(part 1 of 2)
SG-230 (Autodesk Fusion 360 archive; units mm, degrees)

design "OP-1042" references "OP-1042-D", "OP-1040_C", "Washer DIN 125-2 - A 2.2 Steel 100 HV Plain", "OP-1042-J", "OP-1042-M_1", "OP-1042-H", "OP-1042-L_1", "Śruba metryczna M3x10", "Sprezyna naciskowa", "OP-1042-R", "Stożkowy do blach 2,2x6,5", "Do tworzyw 2,2x8", "OP-1040_A_1", "OP-1042-A", "SZKLO OP-1040", "OP-1042-C_1", "Śruba metryczna; M3x5mm-H", "OP-1042-C", "Śruba metryczna; M2x8mm-H", "Uziemienie gnioazdko", "OP-1042-B", "Spring Lock Washer DIN 127 - B 2 Steel 100 HV Plain", "Sprężyna skrętna 1042", "OP-1042-O", "OP-1042-G", "Spring Lock Washer DIN 127 - B 3 Steel 100 HV Plain", "OP-1042-S", "OP-1042-M", "Washer DIN 433-1 - 3.2 - A Steel 100 HV Plain", "bolec", "Hexagon Thin Nut DIN 439-2 - M2 x 0.4 Steel 6 Plain", "B3/BN1046", "OP-1042-L", "OP-1042-F", "OP-1042-P", "OP-1042-H_1", "OP-1040_przycisk", "OP-1042-N", "OP-1040_A", "OP-1040_F"
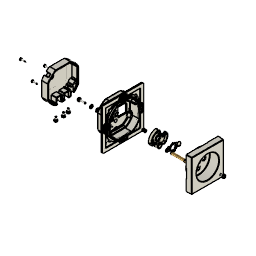
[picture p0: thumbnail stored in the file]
description: https://chmura.techlocal.pl/index.php/s/TPQ2T6wTG2s9XiP
part number: OP-1042 WER.10
component_insert "Component Insert1"
component_insert "Component Insert4"
component_insert "Component Insert5"
component_insert "Component Insert6"
component_insert "Component Insert7"
component_insert "Component Insert8"
component_insert "Component Insert9"
component_insert "Component Insert10"
component_insert "Component Insert11"
component_insert "Component Insert12"
component_insert "Component Insert13"
component_insert "Component Insert14"
component_insert "Component Insert15"
component_insert "Component Insert16"
component_insert "Component Insert17"
component_insert "Component Insert18"
component_insert "Component Insert19"
component_insert "Component Insert20"
joint "Assemble1" alignAngle 0 alignOffsetX 0 alignOffsetY 0 alignOffsetZ 0
component_insert "Component Insert21"
joint "Assemble2" alignAngle 0 alignOffsetX 0 alignOffsetY 0 alignOffsetZ 0
step "Washer1"
joint "Assemble3" alignAngle 0 alignOffsetX 0 alignOffsetY 0 alignOffsetZ 0
step "Washer2"
joint "Assemble4" alignAngle 90 alignOffsetX 0 alignOffsetY 0 alignOffsetZ 0
step "Nut"
joint "Assemble5" alignAngle 0 alignOffsetX 0 alignOffsetY 0 alignOffsetZ 0
step "Screw4"
joint "Assemble6" alignAngle 0 alignOffsetX 0 alignOffsetY 0 alignOffsetZ -1.3
component_insert "Component Insert22"
joint "Assemble7" alignAngle 90 alignOffsetX 0 alignOffsetY 0 alignOffsetZ 0 RotateMinimum 270 RotateMaximum 270
step "Screw5"
joint "Assemble9" alignAngle 0 alignOffsetX 0 alignOffsetY 0 alignOffsetZ 0
step "Screw6"
joint "Assemble10" alignAngle 0 alignOffsetX 0 alignOffsetY 0 alignOffsetZ 0
step "Screw7"
joint "Assemble11" alignAngle 0 alignOffsetX 0 alignOffsetY 0 alignOffsetZ 0
step "Screw8"
joint "Assemble12" alignAngle 0 alignOffsetX 0 alignOffsetY 0 alignOffsetZ 0
step "Screw9"
joint "Assemble13" alignAngle 0 alignOffsetX 0 alignOffsetY 0 alignOffsetZ 0
step "Screw11"
joint "Assemble16" alignAngle 180 alignOffsetX 0 alignOffsetY 0 alignOffsetZ -1
step "Screw12"
joint "Assemble17" alignAngle 180 alignOffsetX 0 alignOffsetY 0 alignOffsetZ -1
joint "Assemble18" alignAngle 0 alignOffsetX 0 alignOffsetY 0 alignOffsetZ 0
joint "Assemble19" alignAngle 0 alignOffsetX 0 alignOffsetY 0 alignOffsetZ 0
joint "Assemble20" alignAngle 0 alignOffsetX 0 alignOffsetY 0 alignOffsetZ 0
joint "Assemble21" alignAngle 0 alignOffsetX 0 alignOffsetY 0 alignOffsetZ 0
joint "Assemble22" alignAngle 180 alignOffsetX 0 alignOffsetY 0 alignOffsetZ -1
joint "Assemble23" alignAngle 180 alignOffsetX 0 alignOffsetY 0 alignOffsetZ -1
joint "Assemble24" alignAngle -90 alignOffsetX 0 alignOffsetY 0 alignOffsetZ 0
joint "Assemble25" alignAngle -90 alignOffsetX 0 alignOffsetY 0 alignOffsetZ 0
joint "Assemble26" alignAngle 0 alignOffsetX 0 alignOffsetY 0 alignOffsetZ 0
joint "Assemble27" alignAngle 180 alignOffsetX 0 alignOffsetY 0 alignOffsetZ -1
joint "Assemble28" alignAngle 180 alignOffsetX 0 alignOffsetY 0 alignOffsetZ -1
joint "Assemble29" alignAngle 250 alignOffsetX -2.5 alignOffsetY 0.5 alignOffsetZ 0
joint "Assemble30" alignAngle 0 alignOffsetX 0 alignOffsetY 0 alignOffsetZ 0
joint "Assemble31" alignAngle 0 alignOffsetX 0 alignOffsetY 0 alignOffsetZ 0
joint "Assemble32" alignAngle 180 alignOffsetX 0 alignOffsetY 0 alignOffsetZ -1
joint "Assemble33" alignAngle 180 alignOffsetX 0 alignOffsetY 0 alignOffsetZ -1
joint "Assemble34" alignAngle 0 alignOffsetX 0 alignOffsetY 0 alignOffsetZ 6
step "Screw14"
joint "Assemble35" alignAngle 180 alignOffsetX 0 alignOffsetY 0 alignOffsetZ -2.5
step "Screw16"
joint "Assemble36" alignAngle 180 alignOffsetX 0 alignOffsetY 0 alignOffsetZ -2.5
step "Screw17"
joint "Assemble37" alignAngle 180 alignOffsetX 0 alignOffsetY 0 alignOffsetZ -2.5
component_insert "Component Insert24"
joint "Assemble38" alignAngle 0 alignOffsetX 0 alignOffsetY 0 alignOffsetZ -1.6
joint "Assemble39" alignAngle 0 alignOffsetX 0 alignOffsetY 0 alignOffsetZ 0
joint "Assemble40" alignAngle 0 alignOffsetX 0 alignOffsetY 0 alignOffsetZ 0
joint "Assemble41" alignAngle 0 alignOffsetX 0 alignOffsetY 0 alignOffsetZ 0
component_insert "Component Insert25"
joint "Assemble42" alignAngle 180 alignOffsetX 0 alignOffsetY 0 alignOffsetZ -12.6
step "Screw18"
joint "Assemble43" alignAngle 0 alignOffsetX 0 alignOffsetY 0 alignOffsetZ -2.6
component_insert "Component Insert26"
component_insert "Component Insert27"
component_insert "Component Insert28"
component_insert "Component Insert29"
joint "Assemble44" alignAngle 0 alignOffsetX 0 alignOffsetY 0 alignOffsetZ 0
joint "Assemble45" alignAngle 0 alignOffsetX 0 alignOffsetY 0 alignOffsetZ 0
component_insert "Component Insert30"
joint "Assemble46" alignAngle 0 alignOffsetX 0 alignOffsetY 0 alignOffsetZ -1.5
joint "Assemble47" alignAngle 180 alignOffsetX 0 alignOffsetY 0 alignOffsetZ -2.5
joint "Assemble48" alignAngle 180 alignOffsetX 0 alignOffsetY 0 alignOffsetZ 2.5
joint "Assemble49" alignAngle 180 alignOffsetX 0 alignOffsetY 0 alignOffsetZ 2.5
joint "Assemble50" alignAngle 0 alignOffsetX 0 alignOffsetY 0 alignOffsetZ 0
component_insert "Component Insert31"
component_insert "Component Insert32"
component_insert "Component Insert33"
joint "Assemble51" alignAngle 0 alignOffsetX 0 alignOffsetY 0 alignOffsetZ 0
joint "Assemble52" alignAngle 0 alignOffsetX 0 alignOffsetY 0 alignOffsetZ 0
component_insert "Component Insert34"
component_insert "Component Insert35"
joint "Assemble53" alignAngle -180 alignOffsetX 0 alignOffsetY 0 alignOffsetZ 0
joint "Assemble54" alignAngle 0 alignOffsetX 0 alignOffsetY 0 alignOffsetZ 0
joint "Assemble55" alignAngle 0 alignOffsetX 0 alignOffsetY 0 alignOffsetZ -1.6
component_insert "Component Insert36"
joint "Assemble57" alignAngle 180 alignOffsetX 0.05 alignOffsetY -0.05 alignOffsetZ -1.8
joint "Assemble58" alignAngle 0 alignOffsetX 0 alignOffsetY 0 alignOffsetZ -1.6
joint "Assemble59" alignAngle 0 alignOffsetX 0 alignOffsetY 0 alignOffsetZ 0
joint "Assemble60" alignAngle 0 alignOffsetX 0 alignOffsetY 0 alignOffsetZ 0
joint "Assemble61" alignAngle 0 alignOffsetX 0 alignOffsetY 0 alignOffsetZ 0
joint "Assemble62" alignAngle 0 alignOffsetX 0 alignOffsetY 0 alignOffsetZ -1.6
joint "Assemble63" alignAngle 0 alignOffsetX 0 alignOffsetY 0 alignOffsetZ 0
joint "Assemble64" alignAngle -90 alignOffsetX 0 alignOffsetY 0 alignOffsetZ 0
joint "Assemble65" alignAngle 180 alignOffsetX 0 alignOffsetY 0 alignOffsetZ 3.5
joint "Assemble66" alignAngle 180 alignOffsetX 0 alignOffsetY 0 alignOffsetZ 3.5
joint "Assemble67" alignAngle 180 alignOffsetX 0 alignOffsetY 0 alignOffsetZ 3.5
joint "Assemble68" alignAngle 180 alignOffsetX 0 alignOffsetY 0 alignOffsetZ 3.5
joint "Assemble69" alignAngle 0 alignOffsetX 0 alignOffsetY 0 alignOffsetZ 0
joint "Assemble70" alignAngle -90 alignOffsetX 0 alignOffsetY 0 alignOffsetZ 0
joint "Assemble71" alignAngle 0 alignOffsetX 0 alignOffsetY 0 alignOffsetZ 0
joint "Assemble72" alignAngle 0 alignOffsetX 0 alignOffsetY 0 alignOffsetZ -0.1
joint "Assemble73" alignAngle 0 alignOffsetX 0 alignOffsetY 0 alignOffsetZ -1.6
joint "Assemble74" alignAngle 0 alignOffsetX 0 alignOffsetY 0 alignOffsetZ 0
joint "Assemble75" alignAngle 0 alignOffsetX 0 alignOffsetY 0 alignOffsetZ 0
joint "Assemble76" alignAngle 0 alignOffsetX 0 alignOffsetY 0 alignOffsetZ -1.6
joint "Assemble77" alignAngle 0 alignOffsetX 0 alignOffsetY 0 alignOffsetZ 0
component_insert "Component Insert37"
joint "Assemble78" alignAngle 0 alignOffsetX 0 alignOffsetY -1.2 alignOffsetZ 0
step "Washer19"
joint "Assemble79" alignAngle 0 alignOffsetX 0 alignOffsetY 0 alignOffsetZ 0
step "Washer20"
joint "Assemble80" alignAngle 0 alignOffsetX 0 alignOffsetY 0 alignOffsetZ 0
joint "Assemble81" alignAngle 0 alignOffsetX 0 alignOffsetY 0 alignOffsetZ -1.6
joint "Assemble82" alignAngle 0 alignOffsetX 0 alignOffsetY 0 alignOffsetZ 0

design "OP-1042-R" references "OP-1042-B"
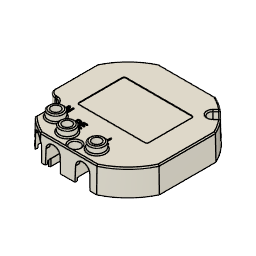
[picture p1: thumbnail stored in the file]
description: arrangementsContainer
external_derived "ExternalDerived1" AlongDistance -1.6 TaperAngle 0 Radius 0.5 Radius 0.5 Radius 2 Radius 1 Linear Dimension-2 20.6 AlongDistance 0.2 TaperAngle 0 Radius 0.8 Radius 0.5 distance 0.9 Radius 0.5 Radius 2 Radius 0.5
step "RemoveFeatures"
step "RemoveFaces1"
step "RemoveFaces2"
fillet "Fillet1" radius 1.25
fillet "Fillet2" radius 2
delete_face "DeleteFace1"
delete_face "DeleteFace2"
delete_face "DeleteFace3"
delete_face "DeleteFace4"
delete_face "DeleteFace5"
delete_face "DeleteFace6"
move_face "MoveFace1"
delete_face "DeleteFace7"
delete_face "DeleteFace8"
offset_faces "OffsetFaces1" distance -13.2
delete_face "DeleteFace9"
move_face "MoveFace2"
move_face "MoveFace3"
move_face "MoveFace4"
fillet "Fillet3" radius 0.5
fillet "Fillet4" radius 0.5
fillet "Fillet5" radius 0.5
fillet "Fillet6" radius 0.5
move_face "MoveFace5"
move_face "MoveFace6"
delete_face "DeleteFace10"
delete_face "DeleteFace11"
move_face "MoveFace7"
sketch "Sketch1" plane through (0, 11.5, 0) normal (0, 1, 0) x axis (-1, 0, 0)
  line L1 (19.3053, -24.5348) -> (19.3053, -43.5348)
  line L2 (50.1053, -22.7348) -> (21.1053, -22.7348)
  line L3 (51.9053, -43.5348) -> (51.9053, -24.5348)
  line L4 (21.1053, -45.3348) -> (50.1053, -45.3348)
  line L5 (41.5666, -61.7513) -> (30.2276, -61.7513)
  line L6 (54.8327, -23.9147) -> (54.8327, -48.4853)
  line L7 (49.8995, -19.4417) -> (51.1656, -18.1756)
  line L8 (47.3056, -14.3156) -> (46.0395, -15.5817)
  line L9 (16.9961, -10.6487) -> (41.5666, -10.6487)
  line L10 (3.73, -42.1572) -> (3.73, -23.9147)
  line L11 (7.1507, -44.9069) -> (6.4792, -44.9069)
  line L12 (9.8879, -56.8807) -> (9.8879, -47.7002)
  line L13 (27.733, -61.7513) -> (16.9961, -61.7513)
  curve K1
  curve K2
  curve K3
  curve K4
  curve K5
  curve K6
  curve K7
  curve K8
  curve K9
  curve K10
  curve K11
  curve K12
  circle C1 centre (22.4803, -56.1272) radius 3.8852
  arc A1 centre (21.1053, -43.5348) radius 1.8 clockwise from (21.1053, -45.3348) to (19.3053, -43.5348)
  arc A2 centre (21.1053, -24.5348) radius 1.8 clockwise from (19.3053, -24.5348) to (21.1053, -22.7348)
  arc A3 centre (50.1053, -24.5348) radius 1.8 clockwise from (50.1053, -22.7348) to (51.9053, -24.5348)
  arc A4 centre (50.1053, -43.5348) radius 1.8 clockwise from (51.9053, -43.5348) to (50.1053, -45.3348)
  arc A5 centre (29.2814, -36.2) radius 28.3513 clockwise from (54.8327, -48.4853) to (41.5666, -61.7513)
  arc A6 centre (29.2814, -36.2) radius 28.3513 clockwise from (51.1656, -18.1756) to (54.8327, -23.9147)
  arc A7 centre (47.9695, -17.5117) radius 2.7294 clockwise from (49.8995, -19.4417) to (46.0395, -15.5817)
  arc A8 centre (29.2814, -36.2) radius 28.3513 clockwise from (41.5666, -10.6487) to (47.3056, -14.3156)
  arc A9 centre (29.2814, -36.2) radius 28.3513 clockwise from (3.73, -23.9147) to (16.9961, -10.6487)
  closed curve K13 centre (6.4805, -42.1559)
  arc A10 centre (7.094, -47.7002) radius 2.7939 clockwise from (7.1507, -44.9069) to (9.8879, -47.7002)
  arc A11 centre (29.2814, -36.2) radius 28.3513 clockwise from (16.9961, -61.7513) to (9.8879, -56.8807)
  arc A12 centre (28.9803, -59.2217) radius 2.8204 clockwise from (27.733, -61.7513) to (30.2276, -61.7513)
  circle C2 centre (14.2237, -52.8962) radius 3.8852
  circle C3 centre (35.4803, -56.1272) radius 3.8852
  point P38 (14.2237, -52.8962)
  point P2 (22.4803, -56.1272)
  point P39 (35.4803, -56.1272)
  vertical P38
  vertical K2
  vertical K6
  vertical K10
  vertical P2
  vertical P39
  equal K1 K2
  equal K5 K6
  equal K9 K10
  equal K5 K9
  equal K1 K5
  dimension "d18" distance P2 K5 = 3 (= "d19")
  dimension "d19" distance P38 K1 = 3
  dimension "d20" distance P39 K9 = 3 (= "d19")
  dimension "d14" Text1-Height = 3
  dimension "d15" Text2-Height = 3
  dimension "d16" Text3-Height = 3
  dimension "d17" distance = 5
delete_face "DeleteFace12"
delete_face "DeleteFace13"
delete_face "DeleteFace14"
extrude "Extrude1" add sketch "Sketch1" along normal blind 0.2
offset_faces "OffsetFaces2" distance -0.2
delete_face "DeleteFace15"
move_face "MoveFace8"
move_face "MoveFace10"
delete_face "DeleteFace16"
fillet "Fillet7" radius 0.5
offset_faces "OffsetFaces3" distance -0.03
draft "Draft1" Angle1 1 Angle2 0
move_face "MoveFace11"
extrude "Extrude2" new body of existing geometry blind 0.2
delete_face "DeleteFace17"
combine "Combine2"
sketch "Sketch7" plane through (0, 9.9, 0) normal (0, -1, 0) x axis (1, 0, 0)
  curve K1 (-9.9653, -17.8349) -> (-9.2431, -17.8508)
  line L1 (-10.4951, -18.3647) -> (-9.9653, -17.8349)
  line L2 (-11.4461, -18.1208) -> (-11.2022, -18.3647)
  line L3 (-10.9163, -16.884) -> (-11.4461, -17.4137)
  curve K2 (-10.9321, -16.1617) -> (-10.9163, -16.884)
  line L4 (-41.2944, -11.8297) -> (-17.2683, -11.8297)
  line L5 (-53.6517, -48.2131) -> (-53.6517, -24.1869)
  curve K3 (-48.5974, -54.5651) -> (-49.3197, -54.5492)
  line L6 (-48.0676, -54.0353) -> (-48.5974, -54.5651)
  line L7 (-47.1167, -54.2792) -> (-47.3605, -54.0353)
  line L8 (-47.6464, -55.516) -> (-47.1167, -54.9863)
  curve K4 (-47.6306, -56.2383) -> (-47.6464, -55.516)
  line L9 (-40.6976, -60.5703) -> (-41.2944, -60.5703)
  line L10 (-40.1976, -52.3597) -> (-40.1976, -60.0705)
  line L11 (-31.2628, -51.8599) -> (-39.6978, -51.8599)
  line L12 (-30.763, -55.6438) -> (-30.763, -52.3597)
  curve K5 (-30.0943, -56.1143) -> (-30.763, -55.6438)
  curve K6 (-27.1976, -55.6438) -> (-27.8663, -56.1143)
  line L13 (-27.1976, -52.3597) -> (-27.1976, -55.6438)
  line L14 (-19.3696, -51.8599) -> (-26.6978, -51.8599)
  line L15 (-19.3696, -51.2663) -> (-19.3696, -51.8599)
  line L16 (-17.8453, -50.7663) -> (-18.8691, -50.7663)
  line L17 (-17.3448, -52.0855) -> (-17.3448, -51.2663)
  line L18 (-17.263, -60.5677) -> (-17.263, -52.3597)
  line L19 (-11.1976, -50.7736) -> (-11.1976, -56.4782)
  line L20 (-14.1884, -50.2738) -> (-11.6975, -50.2738)
  line L21 (-14.6882, -49.0599) -> (-14.6882, -49.774)
  line L22 (-11.4563, -48.5601) -> (-14.1884, -48.5601)
  line L23 (-10.9564, -47.7686) -> (-10.9564, -48.0605)
  line L24 (-6.1603, -43.8379) -> (-7.0256, -43.8379)
  line L25 (-4.911, -24.1869) -> (-4.911, -42.5876)
  curve K7
  curve K8
  curve K9
  curve K10
  closed curve K11 centre (-10.8487, -18.0111)
  closed curve K12 centre (-11.0925, -17.7673)
  arc A1 centre (-29.2814, -36.2) radius 27.1703 clockwise from (-17.2683, -11.8297) to (-10.9321, -16.1617)
  arc A2 centre (-29.2814, -36.2) radius 27.1703 clockwise from (-45.7702, -14.6049) to (-41.2944, -11.8297)
  arc A3 centre (-47.9695, -17.5117) radius 3.645 clockwise from (-45.7702, -14.6049) to (-50.8763, -19.711)
  arc A4 centre (-29.2814, -36.2) radius 27.1703 clockwise from (-53.6517, -24.1869) to (-50.8763, -19.711)
  arc A5 centre (-29.2814, -36.2) radius 27.1703 clockwise from (-49.3197, -54.5492) to (-53.6517, -48.2131)
  closed curve K13 centre (-47.7141, -54.3889)
  closed curve K14 centre (-47.4703, -54.6327)
  arc A6 centre (-29.2814, -36.2) radius 27.1703 clockwise from (-41.2944, -60.5703) to (-47.6306, -56.2383)
  closed curve K15 centre (-40.6978, -60.0703)
  closed curve K16 centre (-39.6975, -52.3601)
  closed curve K17 centre (-31.2631, -52.3601)
  arc A7 centre (-28.9803, -59.2217) radius 3.3011 clockwise from (-30.0943, -56.1143) to (-27.8663, -56.1143)
  closed curve K18 centre (-26.6975, -52.3601)
  closed curve K19 centre (-18.8691, -51.2663)
  closed curve K20 centre (-17.8453, -51.2663)
  closed curve K21 centre (-17.7631, -52.3601)
  arc A8 centre (-29.2814, -36.2) radius 27.1703 clockwise from (-11.1976, -56.4782) to (-17.263, -60.5677)
  closed curve K22 centre (-11.6978, -50.774)
  closed curve K23 centre (-14.1881, -49.7736)
  closed curve K24 centre (-14.1881, -49.0603)
  closed curve K25 centre (-11.4569, -48.0599)
  closed curve K26 centre (-7.0253, -47.7689)
  closed curve K27 centre (-6.1612, -42.5867)
  arc A9 centre (-29.2814, -36.2) radius 27.1703 clockwise from (-9.2431, -17.8508) to (-4.911, -24.1869)
  circle C1 centre (-14.2237, -52.8962) radius 2.1723
  point P14 (-41.2944, -11.8297)
  point P12 (-17.2683, -11.8297)
  coincident P14
  coincident P12 K8
  dimension "d65" Text1-Height = 1.7
  dimension "d66" distance = 2.6
extrude "Extrude8" add sketch "Sketch7" along normal blind 0.1
delete_face "DeleteFace29"
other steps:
derived_base_feature "Derived Base Feature"

design "Spring Lock Washer DIN 127 - B 3 Steel 100 HV Plain"
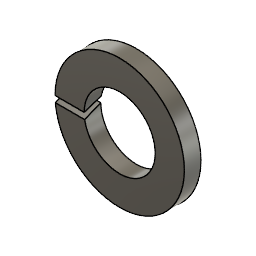
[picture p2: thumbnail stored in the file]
description: Part Number
part number: ---
parameter "adsk_woutdia" = 6.2
parameter "adsk_windia" = 3.4
parameter "adsk_wthick" = 0.8
sketch "Sketch1" plane through (0, 0, 0) normal (0, 0, 1) x axis (1, 0, 0)
  circle C1 centre (0, 0) radius 3.1
  circle C2 centre (0, 0) radius 1.7
  point P1 (0, 0)
  point P2 (0, 0)
  point P3 (0, 0)
  coincident P1 P2
  coincident P1 P3
  dimension "d4" diameter C1 = 6.2 (= "adsk_woutdia")
  dimension "d5" diameter C2 = 3.4 (= "adsk_windia")
extrude "Extrude1" new body sketch "Sketch1" along normal blind 0.8 (= "adsk_wthick")
work_plane "WorkPlane1" RotateAngle 20
work_plane "WorkPlane2" AlongDistance 0.4 (= "adsk_wthick / 2")
sketch "Sketch2" plane through (12.125, -0.1368, 0.3759) normal (0, -0.342, 0.9397) x axis (1, 0, 0)
  line L1 (-12.125, 0) -> (-12.125, 0.2736)
  line L2 (-15.349, 0.2736) -> (-12.125, 0.2736)
  line L3 (-15.349, 0) -> (-12.125, 0)
  line L4 (-15.349, 0.2736) -> (-15.349, 0)
  closed curve K1 centre (-12.125, 0.2736)
  closed curve K2 centre (-12.125, 0)
  point P2 (-12.125, 0.2736)
  point P4 (-12.125, 0.2736)
  point P3 (-12.125, 0)
  point P5 (-12.125, 0)
  coincident P2 P4
  coincident P3 P5
  perpendicular L1 L2
  perpendicular L1 L3
  vertical L4
  dimension "d15" distance L1 L4 = 3.224 (= "adsk_woutdia * 0.52")
extrude "Extrude2" cut sketch "Sketch2" profile of K1 K2 L1 L2 L3 along a picked direction no distance stored
joint_origin "JointOrigin4" OffsetX 0 OffsetY 0 OffsetZ 0 AngleZ 0
joint_origin "JointOrigin6" OffsetX 0 OffsetY 0 OffsetZ 0.8 (= "adsk_wthick") AngleZ 0

design "OP-1042-L_1" references "OP-1042-L"
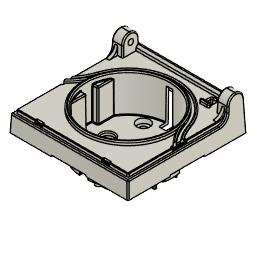
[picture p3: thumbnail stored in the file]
description: arrangementsContainer
external_derived "ExternalDerived1"
delete_face "DeleteFace1"
delete_face "DeleteFace2"
delete_face "DeleteFace3"
delete_face "DeleteFace4"
delete_face "DeleteFace5"
fillet "Fillet1" radius 0.5
fillet "Fillet2" radius 0.5
move_face "MoveFace1"
move_face "MoveFace2"
sketch "Sketch1" plane through (0, 0, 0) normal (0, 0, -1) x axis (1, 0, 0)
  line L1 (-24.85, -27.5351) -> (-24.85, 16.8505)
  line L2 (-24.0537, -27.5351) -> (-24.85, -27.5351)
  line L3 (-22.5551, -32.6087) -> (-22.5551, -29.0337)
  line L4 (12.6671, -32.6714) -> (-22.5564, -32.6714)
  line L5 (12.6671, -28.0098) -> (12.6671, -32.6714)
  line L6 (17.5584, -26.1185) -> (14.5584, -26.1185)
  line L7 (19.4497, -32.6714) -> (19.4497, -28.0098)
  line L8 (22.5564, -32.6714) -> (19.4497, -32.6714)
  line L9 (22.5551, -29.0337) -> (22.5551, -32.6087)
  line L10 (24.85, -27.5351) -> (24.0537, -27.5351)
  line L11 (24.85, 16.8505) -> (24.85, -27.5351)
  line L12 (-24.3505, 17.35) -> (24.3505, 17.35)
  line L13 (-1.5148, -27.9849) -> (-1.5148, -27.8175)
  line L14 (-1.5148, 11.8058) -> (-1.5148, 12.9849)
  line L15 (1.5148, 12.9849) -> (1.5148, 11.8058)
  line L16 (1.5148, -27.8175) -> (1.5148, -27.9849)
  line L17 (-18.2759, -25.3025) -> (-18.6345, -25.3025)
  line L18 (-17.4149, -27.8025) -> (-18.2759, -25.3025)
  line L19 (-17.7714, -27.8025) -> (-17.4149, -27.8025)
  line L20 (-18.4643, -25.7259) -> (-17.7714, -27.8025)
  line L21 (-19.1572, -27.8025) -> (-18.4643, -25.7259)
  line L22 (-19.4955, -27.8025) -> (-19.1572, -27.8025)
  line L23 (-18.6345, -25.3025) -> (-19.4955, -27.8025)
  line L24 (-17.6397, -29.9859) -> (-17.6397, -29.5686)
  line L25 (-17.664, -29.9859) -> (-17.6397, -29.9859)
  curve K1 (-18.4359, -29.6618) -> (-17.664, -29.9859)
  curve K2 (-18.9931, -30.0791) -> (-18.4359, -29.6618)
  curve K3 (-18.6851, -30.462) -> (-18.9931, -30.0791)
  curve K4 (-18.2333, -30.5755) -> (-18.6851, -30.462)
  curve K5 (-17.82, -30.7963) -> (-18.2333, -30.5755)
  curve K6 (-17.658, -31.2481) -> (-17.82, -30.7963)
  curve K7 (-18.4987, -31.9633) -> (-17.658, -31.2481)
  curve K8 (-19.2422, -31.8012) -> (-18.4987, -31.9633)
  line L26 (-19.2422, -31.4041) -> (-19.2422, -31.8012)
  line L27 (-19.2179, -31.4041) -> (-19.2422, -31.4041)
  curve K9 (-18.521, -31.6756) -> (-19.2179, -31.4041)
  curve K10 (-18.0044, -31.2825) -> (-18.521, -31.6756)
  curve K11 (-18.3306, -30.8936) -> (-18.0044, -31.2825)
  curve K12 (-18.8431, -30.7619) -> (-18.3306, -30.8936)
  curve K13 (-19.3395, -30.1318) -> (-18.8431, -30.7619)
  curve K14 (-19.1126, -29.601) -> (-19.3395, -30.1318)
  curve K15 (-18.4602, -29.3741) -> (-19.1126, -29.601)
  curve K16 (-17.6397, -29.5686) -> (-18.4602, -29.3741)
  line L28 (-11.2803, -29.8482) -> (-11.2803, -29.5504)
  line L29 (-12.6782, -30.5127) -> (-11.2803, -29.8482)
  line L30 (-11.2803, -31.1752) -> (-12.6782, -30.5127)
  line L31 (-11.2803, -31.473) -> (-11.2803, -31.1752)
  line L32 (-13.0834, -30.612) -> (-11.2803, -31.473)
  line L33 (-13.0834, -30.4114) -> (-13.0834, -30.612)
  line L34 (-11.2803, -29.5504) -> (-13.0834, -30.4114)
  line L35 (-1.9663, -30.6646) -> (-1.9663, -30.3607)
  line L36 (-2.9124, -30.6646) -> (-1.9663, -30.6646)
  line L37 (-2.9124, -30.3607) -> (-2.9124, -30.6646)
  line L38 (-1.9663, -30.3607) -> (-2.9124, -30.3607)
  line L39 (5.3108, -29.6739) -> (5.3108, -29.4187)
  line L40 (4.857, -29.6739) -> (5.3108, -29.6739)
  line L41 (4.857, -31.3494) -> (4.857, -29.6739)
  line L42 (5.3108, -31.3494) -> (4.857, -31.3494)
  line L43 (5.3108, -31.5783) -> (5.3108, -31.3494)
  curve K17 (4.7942, -31.9268) -> (5.3108, -31.5783)
  line L44 (4.5349, -31.9268) -> (4.7942, -31.9268)
  line L45 (4.5349, -29.6739) -> (4.5349, -31.9268)
  line L46 (4.0912, -29.6739) -> (4.5349, -29.6739)
  line L47 (4.0912, -29.4187) -> (4.0912, -29.6739)
  line L48 (5.3108, -29.4187) -> (4.0912, -29.4187)
  curve K18 (9.2452, -29.7064) -> (8.9454, -30.6687)
  curve K19 (10.0515, -29.366) -> (9.2452, -29.7064)
  curve K20 (10.8578, -29.7064) -> (10.0515, -29.366)
  curve K21 (11.1556, -30.6687) -> (10.8578, -29.7064)
  curve K22 (10.8558, -31.633) -> (11.1556, -30.6687)
  curve K23 (10.0515, -31.9714) -> (10.8558, -31.633)
  curve K24 (9.2452, -31.633) -> (10.0515, -31.9714)
  curve K25 (8.9454, -30.6687) -> (9.2452, -31.633)
  curve K26 (7.9668, -30.3506) -> (7.2193, -30.6099)
  line L49 (8.2484, -30.3506) -> (7.9668, -30.3506)
  line L50 (8.2484, -29.4187) -> (8.2484, -30.3506)
  line L51 (8.5807, -29.4187) -> (8.2484, -29.4187)
  line L52 (8.5807, -31.9187) -> (8.5807, -29.4187)
  line L53 (7.9527, -31.9187) -> (8.5807, -31.9187)
  curve K27 (7.2983, -31.7627) -> (7.9527, -31.9187)
  curve K28 (7.0005, -31.165) -> (7.2983, -31.7627)
  curve K29 (7.2193, -30.6099) -> (7.0005, -31.165)
  line L54 (6.7857, -30.6646) -> (6.7857, -30.3607)
  line L55 (5.8396, -30.6646) -> (6.7857, -30.6646)
  line L56 (5.8396, -30.3607) -> (5.8396, -30.6646)
  line L57 (6.7857, -30.3607) -> (5.8396, -30.3607)
  curve K30 (3.6739, -30.6667) -> (2.8736, -29.366)
  curve K31 (2.8736, -31.9693) -> (3.6739, -30.6667)
  curve K32 (2.0754, -30.6687) -> (2.8736, -31.9693)
  curve K33 (2.8736, -29.366) -> (2.0754, -30.6687)
  line L58 (0.4445, -29.4187) -> (0.4445, -30.2777)
  line L59 (0.7667, -29.4187) -> (0.4445, -29.4187)
  line L60 (0.7667, -30.2777) -> (0.7667, -29.4187)
  line L61 (1.8708, -30.2777) -> (0.7667, -30.2777)
  line L62 (1.8708, -30.6302) -> (1.8708, -30.2777)
  line L63 (0.7525, -31.9187) -> (1.8708, -30.6302)
  line L64 (0.4445, -31.9187) -> (0.7525, -31.9187)
  line L65 (0.4445, -30.5471) -> (0.4445, -31.9187)
  line L66 (0.1467, -30.5471) -> (0.4445, -30.5471)
  line L67 (0.1467, -30.2777) -> (0.1467, -30.5471)
  line L68 (0.4445, -30.2777) -> (0.1467, -30.2777)
  line L69 (-0.1207, -29.7732) -> (-0.1207, -29.4187)
  curve K34 (-0.7244, -30.3749) -> (-0.1207, -29.7732)
  curve K35 (-1.2187, -31.2663) -> (-0.7244, -30.3749)
  curve K36 (-1.0952, -31.5803) -> (-1.2187, -31.2663)
  curve K37 (-0.7892, -31.6816) -> (-1.0952, -31.5803)
  curve K38 (-0.4347, -31.6026) -> (-0.7892, -31.6816)
  curve K39 (-0.1916, -31.4649) -> (-0.4347, -31.6026)
  line L70 (-0.1734, -31.4649) -> (-0.1916, -31.4649)
  line L71 (-0.1734, -31.8214) -> (-0.1734, -31.4649)
  curve K40 (-0.8136, -31.9714) -> (-0.1734, -31.8214)
  curve K41 (-1.5591, -31.2846) -> (-0.8136, -31.9714)
  curve K42 (-1.4294, -30.7842) -> (-1.5591, -31.2846)
  curve K43 (-1.0952, -30.3567) -> (-1.4294, -30.7842)
  curve K44 (-0.4347, -29.7084) -> (-1.0952, -30.3567)
  line L72 (-1.6624, -29.7084) -> (-0.4347, -29.7084)
  line L73 (-1.6624, -29.4187) -> (-1.6624, -29.7084)
  line L74 (-0.1207, -29.4187) -> (-1.6624, -29.4187)
  line L75 (-3.3156, -31.9187) -> (-3.3156, -29.4187)
  line L76 (-3.6478, -31.9187) -> (-3.3156, -31.9187)
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  dimension "d5" Text1-Height = 2.5
extrude "Extrude1" add sketch "Sketch1" along normal blind 0.2
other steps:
derived_base_feature "Derived Base Feature"

design "OP-1042-G"
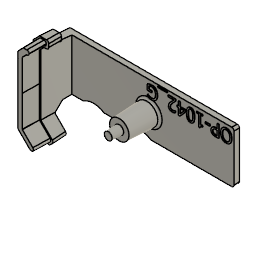
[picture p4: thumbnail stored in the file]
description: Part Number
part number: OP-1042-G
base_feature "Base Feature"

design "OP-1042-O"
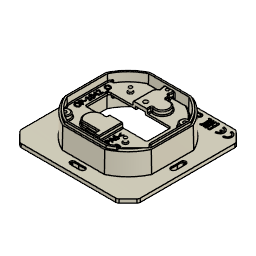
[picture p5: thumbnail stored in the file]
description: Part Number
part number: OP-1042-O
base_feature "Base Feature"

design "Washer DIN 433-1 - 3.2 - A Steel 100 HV Plain"
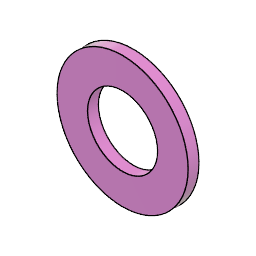
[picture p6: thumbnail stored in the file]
description: Part Number
part number: arrangementsContainer
parameter "adsk_woutdia" = 6
parameter "adsk_windia" = 3.2
parameter "adsk_wthick" = 0.5
sketch "Sketch1" plane through (0, 0, 0) normal (0, 0, 1) x axis (1, 0, 0)
  circle C1 centre (0, 0) radius 3
  circle C2 centre (0, 0) radius 1.6
  point P1 (0, 0)
  point P2 (0, 0)
  point P3 (0, 0)
  coincident P1 P2
  coincident P1 P3
  dimension "d4" diameter C1 = 6 (= "adsk_woutdia")
  dimension "d5" diameter C2 = 3.2 (= "adsk_windia")
extrude "Extrude1" new body sketch "Sketch1" along normal blind 0.5 (= "adsk_wthick")
joint_origin "JointOrigin4" OffsetX 0 OffsetY 0 OffsetZ 0 AngleZ 0
joint_origin "JointOrigin6" OffsetX 0 OffsetY 0 OffsetZ 0.5 (= "adsk_wthick") AngleZ 0

design "OP-1042-M" references "OP-1042-H"
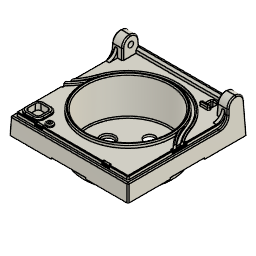
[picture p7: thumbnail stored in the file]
description: Part Number
part number: OP-1042-M
base_feature "Base Feature"
external_derived "ExternalDerived1"
split "Split1"
remove_body "RemoveBody1"
combine "Combine1"
move_face "MoveFace1"
delete_face "DeleteFace1"
delete_face "DeleteFace2"
fillet "Fillet1" radius 0.5
delete_face "DeleteFace7"
delete_face "DeleteFace8"
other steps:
derived_base_feature "Derived Base Feature"

design "Washer DIN 125-2 - A 2.2 Steel 100 HV Plain"
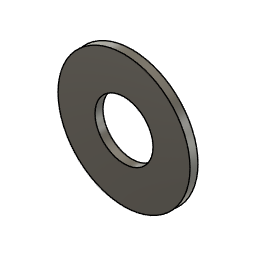
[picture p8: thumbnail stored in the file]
description: Part Number
part number: S_023.02.000.00032
parameter "adsk_woutdia" = 5
parameter "adsk_windia" = 2.2
parameter "adsk_wthick" = 0.3
sketch "Sketch1" plane through (0, 0, 0) normal (0, 0, 1) x axis (1, 0, 0)
  circle C1 centre (0, 0) radius 2.5
  circle C2 centre (0, 0) radius 1.1
  point P1 (0, 0)
  point P2 (0, 0)
  point P3 (0, 0)
  coincident P1 P2
  coincident P1 P3
  dimension "d4" diameter C1 = 5 (= "adsk_woutdia")
  dimension "d5" diameter C2 = 2.2 (= "adsk_windia")
extrude "Extrude1" new body sketch "Sketch1" along normal blind 0.3 (= "adsk_wthick")
joint_origin "JointOrigin4" OffsetX 0 OffsetY 0 OffsetZ 0 AngleZ 0
joint_origin "JointOrigin6" OffsetX 0 OffsetY 0 OffsetZ 0.3 (= "adsk_wthick") AngleZ 0

design "Śruba metryczna; M3x5mm-H"
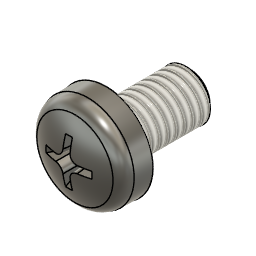
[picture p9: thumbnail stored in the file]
description: Part Number
part number: S_023.01.000.00057
parameter "adsk_nomlen" = 5
parameter "adsk_headh" = 2.4
parameter "adsk_headdia" = 5.6
parameter "adsk_nomdia" = 3
parameter "adsk_phildia" = 3
parameter "adsk_philwidth" = 0.43
parameter "adsk_phildepth" = 1.8
parameter "adsk_thrlen" = 4
parameter "adsk_shnkdia" = 2.7294
parameter "adsk_endpointdia" = 2.3866
parameter "adsk_startlen" = 0.3067
parameter "adsk_ovalrad" = 5
parameter "adsk_headtoprad" = 0.9 (= "adsk_nomdia * 0.3")
parameter "adsk_midfillet" = 0.3 (= "adsk_nomdia * 0.1")
parameter "adsk_headang" = 2
sketch "Sketch1" plane through (0, 0, 0) normal (0, 1, 0) x axis (1, 0, 0)
  line L1 (-1.5, 5) -> (-1.5, 1)
  line L2 (0, 5) -> (-1.5, 5)
  line L3 (0, -2.4) -> (0, 5)
  line L4 (-2.8, 0) -> (-1.3647, 0)
  line L5 (-1.3647, 0.7098) -> (-1.5, 1)
  line L6 (-1.3647, 0) -> (-1.3647, 0.7098)
  line L7 (-2.7449, -1.5792) -> (-2.8, 0)
  arc A1 centre (0, 2.6) radius 5 clockwise from (0, -2.4) to (-2.7449, -1.5792)
  point P1 (0, 0)
  point P2 (0, -2.4)
  point P5 (0, 5)
  point P8 (0, 2.6)
  point P3 (-1.3647, 0)
  point P11 (-1.3647, 0)
  point P6 (-2.8, 0)
  point P9 (-1.5, 1)
  perpendicular L1 L2
  collinear P1 P2 P5
  perpendicular L1 L4
  coincident P1 L4
  vertical L1
  vertical L3
  coincident L3 P8
  perpendicular L4 L6
  coincident P3 P11
  dimension "d9" = 3 (= "adsk_nomdia")
  dimension "d66" = 5.6 (= "adsk_headdia")
  dimension "d67" distance P2 P6 = 2.4 (= "adsk_headh")
  dimension "d68" distance P1 P5 = 5 (= "adsk_nomlen")
  dimension "d70" radius A1 = 5 (= "adsk_ovalrad")
  dimension "d75" = 2.7294 (= "adsk_shnkdia")
  dimension "d77" distance L4 P9 = 1 (= "adsk_nomlen - adsk_thrlen")
  dimension "d78" angle L1 L5 = 155
  dimension "d103" angle L3 L7 = 2 (= "adsk_headang")
revolve "Revolve1" sketch "Sketch1" AlongAngle 360
work_plane "WorkPlane1" AlongDistance 2.4 (= "adsk_headh")
sketch "Sketch2" plane through (0, 0, 2.4) normal (0, 0, 1) x axis (1, 0, 0)
  line L1 (-0.215, 0.215) -> (-0.215, 1.5)
  line L2 (-1.5, 0.215) -> (-0.215, 0.215)
  line L3 (0, 1.5) -> (0, 0)
  line L4 (1.5, 0.215) -> (0.215, 0.215)
  line L5 (0.215, 0.215) -> (0.215, 1.5)
  line L6 (1.5, -0.215) -> (0.215, -0.215)
  line L7 (0.215, -0.215) -> (0.215, -1.5)
  line L8 (-0.215, -0.215) -> (-0.215, -1.5)
  line L9 (-1.5, -0.215) -> (-0.215, -0.215)
  line L10 (0.215, 1.5) -> (-0.215, 1.5)
  line L11 (-1.5, -0.215) -> (-1.5, 0.215)
  line L12 (0.215, -1.5) -> (-0.215, -1.5)
  line L13 (1.5, 0.215) -> (1.5, -0.215)
  line L14 (22.5, 0) -> (1.75, 0)
  circle C1 centre (0, 0) radius 3
  circle C2 centre (0, 0) radius 1.5
  point P2 (0, 0)
  point P7 (0, 0)
  point P3 (-0.215, 1.5)
  point P10 (0.215, 1.5)
  point P4 (-0.215, 0.215)
  point P9 (0.215, 0.215)
  point P5 (-1.5, 0.215)
  point P8 (1.5, 0.215)
  point P6 (0, 1.5)
  perpendicular L1 L2
  coincident P2 P7
  symmetric P3 L3 P10
  symmetric P4 L3 P9
  symmetric P5 L3 P8
  perpendicular L5 L10
  perpendicular L9 L11
  equal L10 L11
  equal L1 L2
  symmetric L2 L9 L14
  horizontal P3 P6
  vertical L3
  symmetric L4 L6 L14
  symmetric L10 L12 L14
  collinear L5 L7
  dimension "d22" distance P3 P10 = 0.43 (= "adsk_philwidth")
  dimension "d57" distance L11 L13 = 3 (= "adsk_phildia")
extrude "Extrude1" new body sketch "Sketch2" profile of L1 L2 L4 L5 L6 L7 L8 L9 L10 L11 L12 L13 C2 no distance stored taper -4
draft "Draft1" Angle1 30 Angle2 0
fillet "Fillet3" radius 0.43 (= "adsk_philwidth")
combine "Combine1"
fillet "Fillet4" radius 0.9 (= "adsk_headtoprad")
thread "Thread1" ThreadOffset 0 ThreadLength 10
fillet "Fillet5" radius 0.3 (= "adsk_midfillet")
sketch "Sketch5" plane through (0, 0, 0) normal (0, 1, 0) x axis (1, 0, 0)
  line L1 (-1.53, 4.6933) -> (-1.53, 5)
  line L2 (-1.1933, 5) -> (-1.53, 4.6933)
  line L3 (0, -2.4) -> (0, 5)
  line L4 (0, 5) -> (-1.53, 5)
  point P5 (0, 5)
  point P7 (0, 5)
  point P4 (-1.1933, 5)
  point P1 (0, 0)
  point P3 (-1.53, 4.6933)
  coincident P5 P7
  perpendicular L3 L4
  coincident P4 L4
  perpendicular L1 L4
  dimension "d89" distance P1 L1 = 1.53 (= "adsk_nomdia * 0.51")
  dimension "d90" distance P3 P4 = 0.3067 (= "adsk_startlen")
  dimension "d91" distance P1 P4 = 1.1933 (= "adsk_endpointdia / 2")
revolve "Revolve2" sketch "Sketch5" AlongAngle 360
joint_origin "JointOrigin2" OffsetX 0 OffsetY 0 OffsetZ 0 AngleZ 0

design "OP-1042-P"
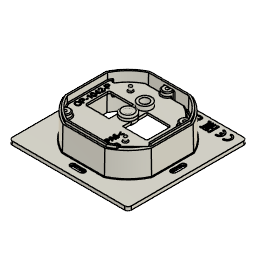
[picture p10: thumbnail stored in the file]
description: Part Number
part number: OP-1042-P
base_feature "Base Feature"
draft "Draft1" Angle1 -2.5 Angle2 0
split_face "SplitFace1"
draft "Draft2" Angle1 1 Angle2 1
draft "Draft3" Angle1 1 Angle2 1
offset_faces "OffsetFaces1" distance -1
sketch "Sketch1" plane through (0, 0, 17.2) normal (0, 0, 1) x axis (-1, 0, 0)
  circle C1 centre (0, 0) radius 4.4371
  circle C2 centre (0, 0) radius 2
extrude "Extrude1" add sketch "Sketch1" profile of C2 against normal blind 0.5
fillet "Fillet1" radius 1
offset_faces "OffsetFaces2" distance -1
offset_faces "OffsetFaces3" distance 0.5
chamfer "Chamfer1" distance 1.3
draft "Draft4" Angle1 0.5 Angle2 1
delete_face "DeleteFace1"
sketch "Sketch2" plane through (0, 0, 14.7) normal (0, 0, 1) x axis (-1, 0, 0)
  line L1 (4, -2.0193) -> (4, -7.2153)
  line L2 (-4, -7.2153) -> (-4, -2.0193)
  line L3 (-17.3882, -7.2153) -> (-4, -7.2153)
  line L4 (-18.3873, 6.2162) -> (-18.3873, -6.2162)
  line L5 (-4, 7.2153) -> (-17.3882, 7.2153)
  line L6 (-4, 2.0193) -> (-4, 7.2153)
  line L7 (4, 7.2153) -> (4, 2.0193)
  line L8 (17.3882, 7.2153) -> (4, 7.2153)
  line L9 (18.3873, -6.2162) -> (18.3873, 6.2162)
  line L10 (4, -7.2153) -> (17.3882, -7.2153)
  line L11 (-16.51, 20.3315) -> (-21.346, 15.5186)
  line L12 (-14.0534, 17.8631) -> (-16.51, 20.3315)
  line L13 (-21.9512, 10.0031) -> (-14.0534, 17.8631)
  line L14 (-23.5909, 11.6506) -> (-21.9512, 10.0031)
  line L15 (-23.5909, -3.6077) -> (-23.5909, 11.6506)
  line L16 (-23.5909, -8.3081) -> (-23.5909, -5.0749)
  line L17 (-3.8417, -21.5057) -> (-11.3257, -21.5057)
  line L18 (11.3257, -21.5057) -> (3.2395, -21.5057)
  curve K1 (20.5745, -12.9406) -> (21.8648, -12.5773)
  line L19 (22.8191, -13.0505) -> (21.8648, -12.5773)
  line L20 (23.5909, 11.83) -> (23.5909, -11.83)
  line L21 (-11.83, 23.5909) -> (11.83, 23.5909)
  line L22 (-13.6228, 20.9299) -> (-13.6228, 20.4996)
  line L23 (-10.6228, 21.9631) -> (-13.6228, 20.9299)
  line L24 (-10.6228, 21.5352) -> (-10.6228, 21.9631)
  line L25 (-13.1147, 20.7038) -> (-10.6228, 21.5352)
  line L26 (-10.6228, 19.8723) -> (-13.1147, 20.7038)
  line L27 (-10.6228, 19.4663) -> (-10.6228, 19.8723)
  line L28 (-13.6228, 20.4996) -> (-10.6228, 19.4663)
  line L29 (-8.168, 22.8018) -> (-8.5254, 22.8018)
  line L30 (-7.3706, 21.1243) -> (-8.168, 22.8018)
  line L31 (-6.5756, 22.8018) -> (-7.3706, 21.1243)
  line L32 (-6.2182, 22.8018) -> (-6.5756, 22.8018)
  line L33 (-7.2515, 20.6381) -> (-6.2182, 22.8018)
  line L34 (-7.4921, 20.6381) -> (-7.2515, 20.6381)
  line L35 (-8.5254, 22.8018) -> (-7.4921, 20.6381)
  curve K2 (-7.5651, 19.1916) -> (-7.2539, 18.2945)
  line L36 (-7.5651, 19.5295) -> (-7.5651, 19.1916)
  line L37 (-8.6834, 19.5295) -> (-7.5651, 19.5295)
  line L38 (-8.6834, 19.9282) -> (-8.6834, 19.5295)
  line L39 (-5.6834, 19.9282) -> (-8.6834, 19.9282)
  line L40 (-5.6834, 19.1746) -> (-5.6834, 19.9282)
  curve K3 (-5.8706, 18.3893) -> (-5.6834, 19.1746)
  curve K4 (-6.5878, 18.032) -> (-5.8706, 18.3893)
  curve K5 (-7.2539, 18.2945) -> (-6.5878, 18.032)
  line L41 (-5.6834, 16.4736) -> (-5.6834, 16.9647)
  line L42 (-8.6834, 15.4623) -> (-5.6834, 16.4736)
  line L43 (-8.6834, 15.8829) -> (-8.6834, 15.4623)
  line L44 (-7.8447, 16.1551) -> (-8.6834, 15.8829)
  line L45 (-7.8447, 17.3002) -> (-7.8447, 16.1551)
  line L46 (-8.6834, 17.5725) -> (-7.8447, 17.3002)
  line L47 (-8.6834, 17.976) -> (-8.6834, 17.5725)
  line L48 (-5.6834, 16.9647) -> (-8.6834, 17.976)
  curve K6 (-8.7466, 14.3196) -> (-8.4646, 13.6487)
  curve K7 (-8.4743, 14.9809) -> (-8.7466, 14.3196)
  curve K8 (-7.3657, 15.3115) -> (-8.4743, 14.9809)
  curve K9 (-6.1113, 14.9833) -> (-7.3657, 15.3115)
  curve K10 (-5.6275, 13.9671) -> (-6.1113, 14.9833)
  curve K11 (-5.6688, 13.6268) -> (-5.6275, 13.9671)
  line L49 (-6.0554, 13.6268) -> (-5.6688, 13.6268)
  line L50 (-6.0554, 13.6438) -> (-6.0554, 13.6268)
  curve K12 (-5.9751, 14.0206) -> (-6.0554, 13.6438)
  curve K13 (-6.9767, 14.8983) -> (-5.9751, 14.0206)
  curve K14 (-6.7677, 14.2735) -> (-6.9767, 14.8983)
  curve K15 (-6.9451, 13.6924) -> (-6.7677, 14.2735)
  curve K16 (-7.7109, 13.3666) -> (-6.9451, 13.6924)
  curve K17 (-8.4646, 13.6487) -> (-7.7109, 13.3666)
  line L51 (-7.2515, 12.8245) -> (-7.4921, 12.8245)
  line L52 (-6.2182, 10.6608) -> (-7.2515, 12.8245)
  line L53 (-6.5756, 10.6608) -> (-6.2182, 10.6608)
  line L54 (-7.3706, 12.3383) -> (-6.5756, 10.6608)
  line L55 (-8.168, 10.6608) -> (-7.3706, 12.3383)
  line L56 (-8.5254, 10.6608) -> (-8.168, 10.6608)
  line L57 (-7.4921, 12.8245) -> (-8.5254, 10.6608)
  curve K18 (-12.1252, 19.3156) -> (-13.686, 18.3553)
  curve K19 (-10.562, 18.3553) -> (-12.1252, 19.3156)
  curve K20 (-12.1228, 17.3974) -> (-10.562, 18.3553)
  curve K21 (-13.686, 18.3553) -> (-12.1228, 17.3974)
  curve K22
  curve K23
  curve K24
  curve K25
  arc A1 centre (0, 0) radius 4.4808 clockwise from (4, -2.0193) to (-4, -2.0193)
  closed curve K26 centre (-17.3863, -6.2143)
  closed curve K27 centre (-17.3863, 6.2143)
  arc A2 centre (0, 0) radius 4.4808 clockwise from (-4, 2.0193) to (4, 2.0193)
  closed curve K28 centre (17.3863, 6.2143)
  closed curve K29 centre (17.3863, -6.2143)
  arc A3 centre (-23.0261, -4.3413) radius 0.9258 clockwise from (-23.5909, -3.6077) to (-23.5909, -5.0749)
  arc A4 centre (-22.1874, -11.5002) radius 3.4871 clockwise from (-23.5909, -8.3081) to (-19.8236, -14.0639)
  closed curve K30 centre (-20.4303, -14.5053)
  arc A5 centre (0, 0) radius 24.3057 clockwise from (-11.3257, -21.5057) to (-19.8182, -14.0716)
  arc A6 centre (-3.842, -22.5079) radius 1.0022 clockwise from (-3.8417, -21.5057) to (-3.536, -21.5535)
  arc A7 centre (-0.3011, -23.0217) radius 3.5525 clockwise from (-3.536, -21.5535) to (2.9339, -21.5535)
  arc A8 centre (3.2398, -22.5079) radius 1.0022 clockwise from (2.9339, -21.5535) to (3.2395, -21.5057)
  arc A9 centre (0, 0) radius 24.3057 clockwise from (20.5745, -12.9406) to (11.3257, -21.5057)
  arc A10 centre (22.3745, -13.9469) radius 1.0006 clockwise from (22.8191, -13.0505) to (22.9093, -13.1012)
  arc A11 centre (0, 0) radius 26.3909 clockwise from (23.5909, -11.83) to (22.9093, -13.1012)
  arc A12 centre (0, 0) radius 26.3909 clockwise from (21.0119, 15.968) to (23.5909, 11.83)
  arc A13 centre (18.6806, 18.6957) radius 3.5882 clockwise from (21.0119, 15.968) to (15.9511, 21.0248)
  arc A14 centre (0, 0) radius 26.3909 clockwise from (11.83, 23.5909) to (15.9511, 21.0248)
  arc A15 centre (0, 0) radius 26.3909 clockwise from (-21.346, 15.5186) to (-11.83, 23.5909)
  circle C1 centre (-12.4364, 13.9524) radius 1.4871
  circle C2 centre (11.9447, -13.4008) radius 1.4913
  circle C3 centre (0, -10) radius 4.0436
  point P51 (23.5909, 11.83)
  point P50 (23.5909, -11.83)
  coincident P51
  coincident P50
  coincident L9
  dimension "d17" Text1-Height = 3
extrude "Extrude2" add sketch "Sketch2" along normal blind 0.1
delete_face "DeleteFace2"

design "Sprezyna naciskowa"
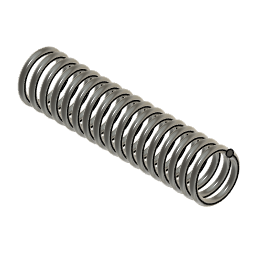
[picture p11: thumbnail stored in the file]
description: Part Number
part number: S_045.00.000.00075

design "OP-1040_A_1" references "OP-1040_A"
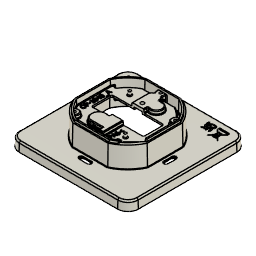
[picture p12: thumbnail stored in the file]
description: arrangementsContainer
external_derived "ExternalDerived1"
delete_face "DeleteFace1"
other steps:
derived_base_feature "Derived Base Feature"

design "OP-1042-N"
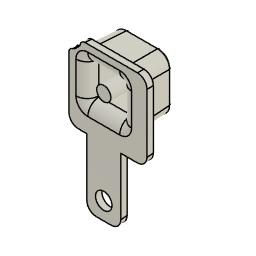
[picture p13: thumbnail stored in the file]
description: Przycisk wysoki
part number: OP-1042-N
base_feature "Base Feature"

design "Do tworzyw 2,2x8"
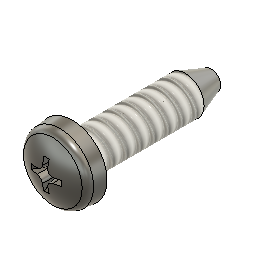
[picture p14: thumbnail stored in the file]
description: Do tworzyw 2,2x8
part number: S_023.05.000.00006
parameter "adsk_nomlen" = 8
parameter "adsk_headh" = 1.6
parameter "adsk_headdia" = 4
parameter "adsk_nomdia" = 2.2
parameter "adsk_phildia" = 1.9
parameter "adsk_philwidth" = 0.31
parameter "adsk_phildepth" = 1.2
parameter "adsk_startlen" = 1.6
parameter "adsk_thrlen" = 8 (= "adsk_nomlen")
parameter "adsk_endpointdia" = 1.1 (= "adsk_nomdia / 2")
parameter "adsk_ovalrad" = 3.2
sketch "Sketch1" plane through (0, 0, 0) normal (0, 1, 0) x axis (1, 0, 0)
  line L1 (-1.1, 8) -> (-1.1, 0)
  line L2 (0, 8) -> (-1.1, 8)
  line L3 (0, -1.6) -> (0, 8)
  line L4 (-2, 0) -> (-1.1, 0)
  line L5 (-1.9157, -0.9632) -> (-2, 0)
  arc A1 centre (0, 1.6) radius 3.2 clockwise from (0, -1.6) to (-1.9157, -0.9632)
  point P1 (0, 0)
  point P2 (0, -1.6)
  point P5 (0, 8)
  point P8 (0, 1.6)
  point P6 (-2, 0)
  perpendicular L1 L2
  collinear P1 P2 P5
  perpendicular L1 L4
  coincident P1 L4
  vertical L1
  vertical L3
  coincident L3 P8
  dimension "d9" = 2.2 (= "adsk_nomdia")
  dimension "d66" = 4 (= "adsk_headdia")
  dimension "d67" distance P2 P6 = 1.6 (= "adsk_headh")
  dimension "d68" distance P1 P5 = 8 (= "adsk_nomlen")
  dimension "d70" radius A1 = 3.2 (= "adsk_ovalrad")
  dimension "d95" angle L4 L5 = 85
revolve "Revolve1" sketch "Sketch1" AlongAngle 360
work_plane "WorkPlane1" AlongDistance 1.6 (= "adsk_headh")
sketch "Sketch2" plane through (0, 0, 1.6) normal (0, 0, 1) x axis (1, 0, 0)
  line L1 (-0.155, 0.155) -> (-0.155, 0.95)
  line L2 (-0.95, 0.155) -> (-0.155, 0.155)
  line L3 (0, 0.95) -> (0, 0)
  line L4 (0.95, 0.155) -> (0.155, 0.155)
  line L5 (0.155, 0.155) -> (0.155, 0.95)
  line L6 (0.95, -0.155) -> (0.155, -0.155)
  line L7 (0.155, -0.155) -> (0.155, -0.95)
  line L8 (-0.155, -0.155) -> (-0.155, -0.95)
  line L9 (-0.95, -0.155) -> (-0.155, -0.155)
  line L10 (0.155, 0.95) -> (-0.155, 0.95)
  line L11 (-0.95, -0.155) -> (-0.95, 0.155)
  line L12 (0.155, -0.95) -> (-0.155, -0.95)
  line L13 (0.95, 0.155) -> (0.95, -0.155)
  line L14 (22.5, 0) -> (1.75, 0)
  circle C1 centre (0, 0) radius 3
  circle C2 centre (0, 0) radius 1.5
  point P2 (0, 0)
  point P7 (0, 0)
  point P3 (-0.155, 0.95)
  point P10 (0.155, 0.95)
  point P4 (-0.155, 0.155)
  point P9 (0.155, 0.155)
  point P5 (-0.95, 0.155)
  point P8 (0.95, 0.155)
  point P6 (0, 0.95)
  perpendicular L1 L2
  coincident P2 P7
  symmetric P3 L3 P10
  symmetric P4 L3 P9
  symmetric P5 L3 P8
  perpendicular L5 L10
  perpendicular L9 L11
  equal L10 L11
  equal L1 L2
  symmetric L2 L9 L14
  horizontal P3 P6
  vertical L3
  symmetric L4 L6 L14
  symmetric L10 L12 L14
  collinear L5 L7
  dimension "d22" distance P3 P10 = 0.31 (= "adsk_philwidth")
  dimension "d57" distance L11 L13 = 1.9 (= "adsk_phildia")
extrude "Extrude1" new body sketch "Sketch2" profile of L1 L2 L4 L5 L6 L7 L8 L9 L10 L11 L12 L13 no distance stored taper -4
draft "Draft1" Angle1 30 Angle2 0
fillet "Fillet3" radius 0.31 (= "adsk_philwidth")
combine "Combine1"
fillet "Fillet5" radius 0.5333 (= "adsk_headh / 3")
thread "Thread2" ThreadOffset 0 ThreadLength 8 (= "adsk_thrlen")
sketch "Sketch5" plane through (0, 0, 0) normal (0, 1, 0) x axis (1, 0, 0)
  line L1 (-1.122, 6.4) -> (-1.122, 8)
  line L2 (-0.55, 8) -> (-1.122, 6.4)
  line L3 (0, -1.6) -> (0, 8)
  line L4 (0, 8) -> (-1.122, 8)
  point P5 (0, 8)
  point P7 (0, 8)
  point P4 (-0.55, 8)
  point P1 (0, 0)
  point P3 (-1.122, 6.4)
  coincident P5 P7
  perpendicular L1 L4
  coincident P4 L4
  perpendicular L3 L4
  dimension "d92" distance P1 L1 = 1.122 (= "adsk_nomdia * 0.51")
  dimension "d93" distance P3 P4 = 1.6 (= "adsk_startlen")
  dimension "d94" distance P1 P4 = 0.55 (= "adsk_endpointdia / 2")
revolve "Revolve2" sketch "Sketch5" AlongAngle 360
joint_origin "JointOrigin2" OffsetX 0 OffsetY 0 OffsetZ 0 AngleZ 0

design "B3/BN1046"
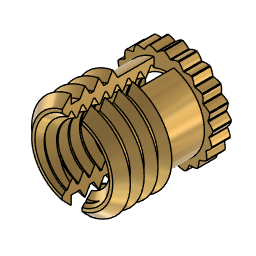
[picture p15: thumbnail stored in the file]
description: Insert M3x4.72mm
part number: S_045.00.000.00084
base_feature "Base Feature"

design "OP-1042-C"
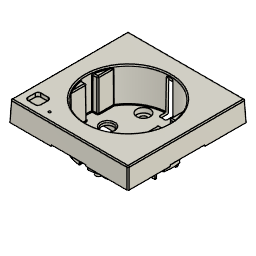
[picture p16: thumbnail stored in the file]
description: Part Number
part number: OP-1042-C
base_feature "Base Feature"
move_face "MoveFace1" TranslateX 0.85 TranslateY 0 TranslateZ 0
move_face "MoveFace2" TranslateX -0.4 TranslateY 0 TranslateZ 0
move_face "MoveFace3" TranslateX 0.4 TranslateY 0 TranslateZ 0
move_face "MoveFace4" TranslateX -0.85 TranslateY 0 TranslateZ 0

design "OP-1042-B"
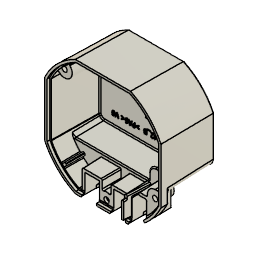
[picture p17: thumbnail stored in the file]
description: Part Number
part number: OP-1042-B
base_feature "Base Feature"
derived_base_feature "Derived Base Feature"
combine "Combine1"

design "OP-1042-I"
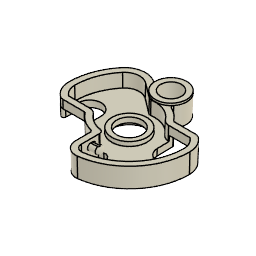
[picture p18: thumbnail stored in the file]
description: Part Number
part number: OP-1042-I
base_feature "Base Feature"
draft "Draft1" Angle1 3 Angle2 1
offset_faces "OffsetFaces1" distance 1
offset_faces "OffsetFaces2" distance -0.3
extrude "Extrude1" add of existing geometry blind 0.1
delete_face "DeleteFace1"
offset_faces "OffsetFaces3" distance 0.14
chamfer "Chamfer1" distance 0.6
delete_face "DeleteFace2"
sketch "Sketch1" plane through (0, 0, -18.5) normal (0, 0, 1) x axis (-1, 0, 0)
  line L1 (0.0003, -0.0279) -> (0.0003, -0.2919)
  line L2 (0.0005, 3.9522) -> (0.0005, 3.0279)
  line L3 (-10.6405, -10.3556) -> (-11.609, -10.3556)
  line L4 (-10.6405, -10.0024) -> (-10.6405, -10.3556)
  line L5 (-7.4519, -10.3556) -> (-7.4519, -9.3351)
  line L6 (-6.4833, -10.3556) -> (-7.4519, -10.3556)
  line L7 (5.1321, -16.4349) -> (1.4912, -13.6733)
  line L8 (10.6405, -4.6444) -> (11.609, -4.6444)
  line L9 (10.6405, -4.9976) -> (10.6405, -4.6444)
  line L10 (7.4519, -4.6444) -> (7.4519, -5.6649)
  line L11 (6.4833, -4.6444) -> (7.4519, -4.6444)
  line L12 (0.0003, -0.2919) -> (0.0003, -0.4708)
  line L13 (6.7504, -7.548) -> (12.2496, -7.548)
  line L14 (6.6499, -1.7867) -> (6.7504, -7.548)
  line L15 (12.3501, -1.7867) -> (6.6499, -1.7867)
  line L16 (12.2496, -7.548) -> (12.3501, -1.7867)
  line L17 (-12.2496, -7.452) -> (-6.7504, -7.452)
  line L18 (-12.3744, -14.6033) -> (-12.2496, -7.452)
  line L19 (-6.6256, -14.6033) -> (-12.3744, -14.6033)
  line L20 (-6.7504, -7.452) -> (-6.6256, -14.6033)
  arc A1 centre (0, -7.5) radius 7.4721 clockwise from (-1.2393, -0.1314) to (0.0003, -0.0279)
  arc A2 centre (-1.4927, 1.3754) radius 1.5279 clockwise from (-1.2393, -0.1314) to (-1.7461, 2.8821)
  arc A3 centre (0, -7.5) radius 10.5279 clockwise from (-1.7461, 2.8821) to (0.0005, 3.0279)
  arc A4 centre (-1.4995, 3.9523) radius 1.5 clockwise from (-1.6942, 5.4396) to (0.0005, 3.9522)
  arc A5 centre (0, -7.5) radius 13.05 clockwise from (-13.05, -7.5) to (-1.6942, 5.4396)
  arc A6 centre (-9.5, -7.5) radius 3.55 clockwise from (-11.609, -10.3556) to (-13.05, -7.5)
  arc A7 centre (-9.5, -7.5) radius 2.75 clockwise from (-10.6405, -10.0024) to (-7.4519, -9.3351)
  arc A8 centre (-6.4833, -12.3556) radius 2 clockwise from (-6.4833, -10.3556) to (-4.8825, -11.1567)
  arc A9 centre (0, -7.5) radius 6.1 clockwise from (0.9243, -13.5296) to (-4.8825, -11.1567)
  arc A10 centre (1.0379, -14.2709) radius 0.75 clockwise from (0.9243, -13.5296) to (1.4912, -13.6733)
  arc A11 centre (7.2774, -13.6065) radius 3.55 clockwise from (9.9969, -15.8884) to (5.1321, -16.4349)
  arc A12 centre (0, -7.5) radius 13.05 clockwise from (13.05, -7.5) to (9.9969, -15.8884)
  arc A13 centre (9.5, -7.5) radius 3.55 clockwise from (11.609, -4.6444) to (13.05, -7.5)
  arc A14 centre (9.5, -7.5) radius 2.75 clockwise from (10.6405, -4.9976) to (7.4519, -5.6649)
  arc A15 centre (6.4833, -2.6444) radius 2 clockwise from (6.4833, -4.6444) to (4.8825, -3.8433)
  arc A16 centre (0, -7.5) radius 6.1 clockwise from (0.8594, -1.4608) to (4.8825, -3.8433)
  arc A17 centre (1.0003, -0.4708) radius 1 clockwise from (0.8594, -1.4608) to (0.0003, -0.4708)
  circle C1 centre (0, -7.5) radius 4.2131
  point P41 (12.2496, -7.548)
  point P42 (6.7504, -7.548)
  point P45 (-6.7504, -7.452)
  point P46 (-12.2496, -7.452)
  horizontal L13
  horizontal L15
  coincident A14 P41
  coincident A14 P42
  tangent A14 L16
  horizontal L17
  horizontal L19
  coincident A7 P45
  tangent A7 L20
  coincident A7 P46
  tangent A14 L14
  tangent A7 L18
  dimension "d13" angle L14 L16 = 2
  dimension "d14" angle L18 L20 = 2 (= "d13")
extrude "Extrude2" cut sketch "Sketch1" profile of A6 L3 L4 A7 L5 L6 A13 L8 L9 A14 L10 L11 L13 L14 L15 L16 L17 L18 L19 L20 against normal blind 7 taper 1.5
delete_face "DeleteFace3"
delete_face "DeleteFace4"
fillet "Fillet1" radius 0.5

design "OP-1042-S" references "OP-1042-P"
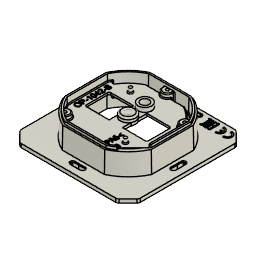
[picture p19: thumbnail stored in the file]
description: arrangementsContainer
derived_base_feature "Derived Base Feature1"
external_derived "ExternalDerived2"
split "Split1"
split "Split2"
remove_body "RemoveBody1"
combine "Combine1"
remove_body "RemoveBody2"
delete_face "DeleteFace1"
